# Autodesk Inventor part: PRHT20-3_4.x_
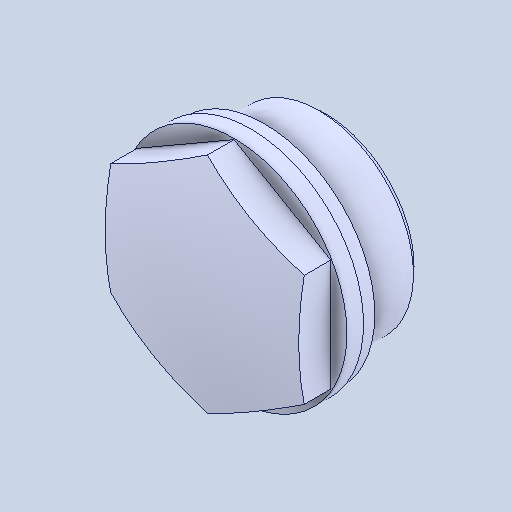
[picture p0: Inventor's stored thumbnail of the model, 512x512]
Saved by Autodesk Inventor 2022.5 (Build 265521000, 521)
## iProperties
Created: 2024-05
Part Number: PRHT20-3_4.x_
Material: 一般
Document SubType Name: Modeling
Designer: ImaoCorp
Density: 1 g/cm^3
Appearance: 既定
Author: ImaoCorp
Sending System: SOLIDWORKS 2022-2022290
MC: AMD64
MC_MODEL: Intel64 Family 6 Model 60 Stepping 3, GenuineIntel
OS: Windows_NT
FRU: Parasolid Version 33.1, build 260,  4-25-2022
FORMAT: text
GUISE: transmit
KEY: FILEPRHT20-3_4.x_t
DATE: Mon May 20 16:41:22 2024
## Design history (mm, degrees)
feature "Base1"
node "ソリッド1"
